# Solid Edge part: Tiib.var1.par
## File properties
Author: jaanm
Template: Ansi Metric part.par
Last saved by: jaanm
Revision: 10
Application: Solid Edge
Accuracy: 0,990
Face Style: Model Default
Coef. of Thermal Exp: 0.0
Thermal Conductivity: 0.0
Specific Heat: 0.0
Modulus of Elasticity: 0.0
Poisson's Ratio: 0.0
Yield Stress: 0.0
Ultimate Stress: 0.0
Elongation: 0.0
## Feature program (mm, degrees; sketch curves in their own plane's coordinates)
make body feature "unnamed MakeBodyFeature 1"
sketch for "ExtrudedProtrusion_1" #1 plane through (0, 0, 0) normal (1, 0, 0) x-axis (0, 1, 0)
  circle centre (100, 0) radius 5
sketch for "ExtrudedProtrusion_1" #2 plane through (0, 0, 0) normal (1, 0, 0) x-axis (0, 1, 0)
  circle centre (0, 0) radius 5
extrude "ExtrudedProtrusion_1" add finite 20 along -normal
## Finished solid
Body 1: solid body, 10 faces, 15 edges, 7 vertices.
  Faces by surface: spline 5, plane 3, cylinder 2
  Edges by curve: circle 5, spline 5, curve on surface 4, line 1
Body 2: solid body, 6 faces, 11 edges, 7 vertices.
  Faces by surface: spline 5, plane 1
  Edges by curve: spline 5, curve on surface 4, circle 1, line 1
Bounding box of the edges (mm; curved faces can reach further): 1533.444 x 504.454 x 268.192, from (-20, -172.3664, -48.767) to (1513.4443, 332.0881, 219.4251).
Cylindrical faces by radius (mm): R5 x2
Planar faces by outward normal: -x 4
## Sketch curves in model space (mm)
arc centre (1503.4443, 87.8397, 219.4251) radius 10 from (1513.4443, 87.8397, 219.4251) through (1503.148, 77.8441, 219.4251) to (1493.4443, 87.8397, 219.4251)
line (1513.4443, 314.6539, 219.4251) -> (1513.4443, 87.8397, 219.4251)
arc centre (1503.4443, 314.6539, 219.4251) radius 10 from (1493.4443, 314.6539, 219.4251) through (1503.7406, 324.6495, 219.4251) to (1513.4443, 314.6539, 219.4251)
line (1493.4443, 314.6539, 219.4251) -> (1493.4443, 87.8397, 219.4251)
line (1200, 11.604, -8.7699) -> (1200, 214.4412, -8.7699)
arc centre (1200, 214.4412, -328.0918) radius 319.3219 from (1200, 214.4412, -8.7699) through (1200, 266.7854, -13.0893) to (1200, 317.7136, -25.9307)
arc centre (1200, 308.0424, -13.5446) radius 15.7146 from (1200, 317.7136, -25.9307) through (1200, 323.5954, -11.2965) to (1200, 314.6539, 0.7115)
arc centre (1200, 202.57, -240.9727) radius 266.4096 from (1200, 314.6539, 0.7115) through (1200, 266.2226, 17.7209) to (1200, 215.4283, 25.1264)
line (1200, 215.4283, 25.1264) -> (1200, -58.996, 38.387)
arc centre (1200, -74.3468, -279.2933) radius 318.051 from (1200, -58.996, 38.387) through (1200, -99.1835, 37.7864) to (1200, -138.9745, 32.1223)
arc centre (1200, -125.4022, -2.0183) radius 36.7394 from (1200, -138.9745, 32.1223) through (1200, -159.1743, -16.4832) to (1200, -110.0546, -35.3984)
arc centre (1200, 11.604, -299.9968) radius 291.227 from (1200, -110.0546, -35.3984) through (1200, -50.6653, -15.5049) to (1200, 11.604, -8.7699)
line (0, 11.2075, -19.7141) -> (0, 214.0447, -19.7141)
arc centre (0, 214.0447, -329.036) radius 309.3219 from (0, 214.0447, -19.7141) through (0, 267.003, -24.2812) to (0, 318.3975, -37.8478)
arc centre (0, 307.646, -14.4888) radius 25.7146 from (0, 318.4646, 8.8392) through (0, 333.3605, -14.5258) to (0, 318.3975, -37.8478)
arc centre (0, 202.1735, -241.9169) radius 276.4096 from (0, 318.4646, 8.8392) through (0, 268.2154, 26.4871) to (0, 215.5145, 34.1705)
line (0, 215.5145, 34.1705) -> (0, -58.9098, 47.4311)
arc centre (0, -74.7433, -280.2375) radius 328.051 from (0, -58.9098, 47.4311) through (0, -100.7721, 46.7792) to (0, -142.2105, 40.8008)
arc centre (0, -125.7987, -2.9625) radius 46.7394 from (0, -106.2736, -45.4282) through (0, -168.9413, -20.9426) to (0, -142.2105, 40.8008)
arc centre (0, 11.2075, -300.941) radius 281.227 from (0, -106.2736, -45.4282) through (0, -48.9236, -26.2178) to (0, 11.2075, -19.7141)
circle centre (0, 100, 0) radius 5
circle centre (0, 0, 0) radius 5
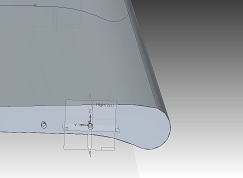
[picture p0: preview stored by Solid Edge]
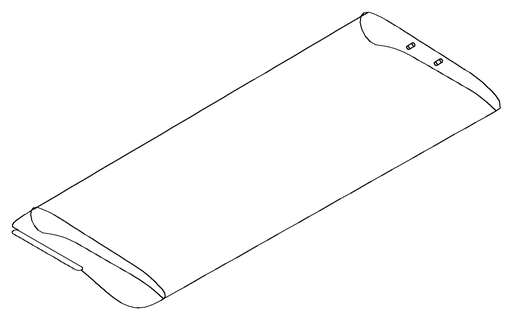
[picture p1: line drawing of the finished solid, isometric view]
